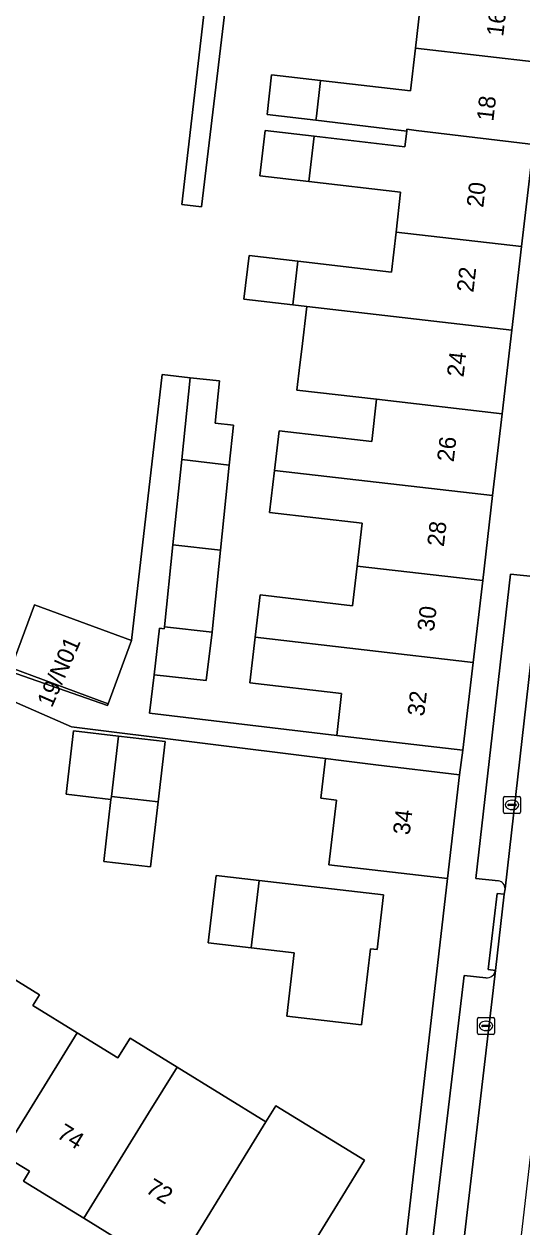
# Model space of a CAD drawing. Extents: x 161692 to 162379, y 380760 to 381678.
# Drawn here: x 161919.9 to 161949.3, y 381028.6 to 381099.9 of the extents above; entities that cross this region are included whole.
import ezdxf

# ---------------------------------------------------------------- set-up
doc = ezdxf.new("R2010")
doc.units = 0
for name, color, linetype in [('IMGEO_Erf', 7, 'Continuous'), ('IMGEO_Kolk', 7, 'Continuous'), ('IMGEO_Pand', 7, 'Continuous'), ('IMGEO_Pand_nummerreeks', 7, 'Continuous'), ('IMGEO_Parkeervlak_open', 7, 'Continuous'), ('IMGEO_Rijbaan_lokaal_open', 7, 'Continuous'), ('IMGEO_Voetpad_open', 7, 'Continuous')]:
    doc.layers.add(name, color=color, linetype=linetype)

msp = doc.modelspace()

# ---------------------------------------------------------------- linework, layer by layer
at = {"layer": 'IMGEO_Erf'}
for points in [[(161934.58, 381124.356), (161930.357, 381089.033), (161929.205, 381089.166), (161932.426, 381116.991)], [(161896.944, 381069.188), (161924.793, 381059.467), (161924.831, 381059.577), (161919.079, 381061.699), (161920.461, 381065.447), (161926.214, 381063.326), (161928.04, 381079.099), (161929.69, 381078.908), (161931.424, 381078.729), (161931.164, 381076.203), (161932.252, 381076.09), (161932.008, 381073.722), (161931.489, 381068.676), (161930.992, 381063.85), (161930.987, 381063.815), (161930.641, 381060.951), (161927.56, 381061.295), (161927.291, 381059.02), (161938.372, 381057.691), (161938.661, 381060.182), (161933.228, 381060.814), (161933.543, 381063.52), (161933.834, 381066.027), (161939.306, 381065.391), (161939.579, 381067.74), (161939.874, 381070.274), (161934.4, 381070.911), (161934.691, 381073.412), (161934.965, 381075.765), (161940.448, 381075.127), (161940.739, 381077.631), (161936.02, 381078.176), (161936.195, 381079.674), (161936.303, 381080.6), (161936.598, 381083.126), (161935.772, 381083.222), (161932.88, 381083.556), (161933.18, 381086.143), (161936.072, 381085.807), (161941.611, 381085.163), (161941.887, 381087.54), (161942.162, 381089.9), (161936.719, 381090.533), (161933.822, 381090.87), (161934.134, 381093.558), (161937.031, 381093.223), (161942.416, 381092.6), (161942.521, 381093.512), (161937.14, 381094.163), (161934.245, 381094.513), (161934.518, 381096.867), (161937.415, 381096.53), (161942.739, 381095.911), (161943.034, 381098.447), (161943.315, 381100.866)], [(161944.934, 381049.22), (161939.968, 381049.797), (161937.906, 381050.037), (161938.359, 381053.871), (161937.434, 381053.988), (161937.711, 381056.326), (161922.667, 381058.201), (161917.5, 381060.471)], [(161941.233, 381016.938), (161944.934, 381049.22)], [(161918.09, 381043.966), (161920.768, 381042.317), (161920.378, 381041.684), (161922.995, 381040.073), (161925.41, 381038.587), (161926.13, 381039.756), (161928.914, 381038.042), (161934.18, 381034.801), (161934.766, 381035.752), (161940.015, 381032.521), (161938.727, 381030.429), (161933.91, 381022.602), (161930.356, 381024.789), (161930.723, 381025.385), (161929.03, 381026.427), (161927.333, 381027.472), (161926.969, 381026.881), (161923.395, 381029.081), (161919.818, 381031.283), (161920.176, 381031.865), (161918.558, 381032.86)]]:
    msp.add_lwpolyline(points, dxfattribs=at)
for points in [[(161924.573, 381050.233), (161925, 381053.907), (161922.34, 381054.216), (161922.775, 381057.964), (161925.435, 381057.655), (161928.212, 381057.332), (161927.797, 381053.759), (161927.35, 381049.911)], [(161935.409, 381041.052), (161935.844, 381044.815), (161933.312, 381045.109), (161930.758, 381045.406), (161931.222, 381049.4), (161933.772, 381049.104), (161941.155, 381048.246), (161940.778, 381045.005), (161940.37, 381045.052), (161939.845, 381040.536)]]:
    msp.add_lwpolyline(points, close=True, dxfattribs=at)
at = {"layer": 'IMGEO_Kolk'}
for p, q in [((161948.26, 381053.155), (161948.26, 381054.007)), ((161948.335, 381054.081), (161949.187, 381054.081)), ((161948.748, 381053.861), (161948.773, 381053.861)), ((161949.261, 381054.007), (161949.261, 381053.155)), ((161949.187, 381053.081), (161948.335, 381053.081)), ((161948.519, 381053.575), (161948.519, 381053.587)), ((161948.957, 381053.538), (161948.559, 381053.538)), ((161948.562, 381053.624), (161948.96, 381053.624)), ((161948.771, 381053.301), (161948.746, 381053.301)), ((161949.003, 381053.587), (161949.003, 381053.575)), ((161946.718, 381040.056), (161946.718, 381040.908)), ((161946.793, 381040.982), (161947.645, 381040.982)), ((161947.719, 381040.908), (161947.719, 381040.056)), ((161946.977, 381040.476), (161946.977, 381040.488)), ((161947.415, 381040.439), (161947.017, 381040.439)), ((161947.02, 381040.525), (161947.418, 381040.525)), ((161947.229, 381040.202), (161947.204, 381040.202)), ((161947.206, 381040.762), (161947.231, 381040.762)), ((161947.461, 381040.488), (161947.461, 381040.476)), ((161947.645, 381039.982), (161946.793, 381039.982))]:
    msp.add_line(p, q, dxfattribs=at)
for points in [[(161948.26, 381053.155), (161948.26, 381054.007)], [(161948.335, 381054.081), (161949.187, 381054.081)], [(161949.261, 381054.007), (161949.261, 381053.155)], [(161949.187, 381053.081), (161948.335, 381053.081)], [(161946.718, 381040.056), (161946.718, 381040.908)], [(161946.793, 381040.982), (161947.645, 381040.982)], [(161947.719, 381040.908), (161947.719, 381040.056)], [(161947.645, 381039.982), (161946.793, 381039.982)]]:
    msp.add_lwpolyline(points, dxfattribs=at)
for centre, radius, start, end in [((161948.337, 381054.005), 0.0765, 91.55205, 178.44795), ((161948.337, 381054.005), 0.0765, 91.55205, 178.44795), ((161949.185, 381054.005), 0.0765, 1.55205, 88.44795), ((161949.185, 381054.005), 0.0765, 1.55205, 88.44795), ((161948.337, 381053.157), 0.0765, 181.55205, 268.44795), ((161948.337, 381053.157), 0.0765, 181.55205, 268.44795), ((161948.559, 381053.584), 0.0403, 85.87752, 175.75265), ((161948.556, 381053.574), 0.0366, 178.93798, 274.71019), ((161948.96, 381053.581), 0.043, 264.86636, 352.45326), ((161948.964, 381053.586), 0.0386, 1.73085, 96.63898), ((161949.185, 381053.157), 0.0765, 271.55205, 358.44795), ((161949.185, 381053.157), 0.0765, 271.55205, 358.44795), ((161946.795, 381040.906), 0.0765, 91.55205, 178.44795), ((161946.795, 381040.906), 0.0765, 91.55205, 178.44795), ((161947.643, 381040.906), 0.0765, 1.55205, 88.44795), ((161947.643, 381040.906), 0.0765, 1.55205, 88.44795), ((161947.017, 381040.485), 0.0403, 85.87752, 175.75265), ((161947.014, 381040.475), 0.0366, 178.93798, 274.71019), ((161947.418, 381040.482), 0.043, 264.86636, 352.45326), ((161947.422, 381040.487), 0.0386, 1.73085, 96.63898), ((161946.795, 381040.058), 0.0765, 181.55205, 268.44795), ((161946.795, 381040.058), 0.0765, 181.55205, 268.44795), ((161947.643, 381040.058), 0.0765, 271.55205, 358.44795), ((161947.643, 381040.058), 0.0765, 271.55205, 358.44795)]:
    msp.add_arc(centre, radius, start, end, dxfattribs=at)
for centre, major_axis, ratio, start_param, end_param in [((161948.747, 381053.581), (-0.387, 0.002), 0.722429, 4.712389, 7.853982), ((161948.772, 381053.581), (-0.39, 0.002), 0.717154, 1.570796, 4.712389), ((161947.205, 381040.482), (-0.387, 0.002), 0.722429, 4.712389, 7.853982), ((161947.23, 381040.482), (-0.39, 0.002), 0.717154, 1.570796, 4.712389)]:
    msp.add_ellipse(centre, major_axis=major_axis, ratio=ratio, start_param=start_param, end_param=end_param, dxfattribs=at)
at = {"layer": 'IMGEO_Pand'}
for points in [[(161951.18, 381102.61), (161938.291, 381104.099), (161937.987, 381101.486), (161943.315, 381100.866), (161943.034, 381098.447), (161950.594, 381097.573)], [(161950.594, 381097.573), (161943.034, 381098.447), (161942.739, 381095.911), (161937.415, 381096.53), (161937.169, 381094.409), (161937.154, 381094.285), (161937.14, 381094.163), (161942.521, 381093.512), (161942.535, 381093.634), (161943.075, 381093.569), (161950.03, 381092.727)], [(161937.415, 381096.53), (161934.518, 381096.867), (161934.245, 381094.513), (161937.14, 381094.163), (161937.154, 381094.285), (161937.169, 381094.409)], [(161937.031, 381093.223), (161934.134, 381093.558), (161933.822, 381090.87), (161936.719, 381090.533)], [(161950.03, 381092.727), (161943.075, 381093.569), (161942.535, 381093.634), (161942.521, 381093.512), (161942.416, 381092.6), (161937.031, 381093.223), (161936.719, 381090.533), (161942.162, 381089.9), (161941.887, 381087.54), (161949.327, 381086.68)], [(161949.327, 381086.68), (161941.887, 381087.54), (161941.611, 381085.163), (161936.072, 381085.807), (161935.772, 381083.222), (161936.598, 381083.126), (161948.751, 381081.721)], [(161936.072, 381085.807), (161933.18, 381086.143), (161932.88, 381083.556), (161935.772, 381083.222)], [(161948.751, 381081.721), (161936.598, 381083.126), (161936.303, 381080.6), (161936.195, 381079.674), (161936.02, 381078.176), (161940.739, 381077.631), (161948.175, 381076.772)], [(161929.189, 381074.048), (161932.008, 381073.722), (161932.252, 381076.09), (161931.164, 381076.203), (161931.424, 381078.729), (161929.69, 381078.908)], [(161934.691, 381073.412), (161947.611, 381071.919), (161948.175, 381076.772), (161940.739, 381077.631), (161940.448, 381075.127), (161934.965, 381075.765)], [(161931.489, 381068.676), (161932.008, 381073.722), (161929.189, 381074.048), (161928.669, 381069.002)], [(161934.691, 381073.412), (161934.4, 381070.911), (161939.874, 381070.274), (161939.579, 381067.74), (161947.025, 381066.879), (161947.611, 381071.919)], [(161928.169, 381064.141), (161930.987, 381063.815), (161930.992, 381063.85), (161931.489, 381068.676), (161928.669, 381069.002)], [(161946.46, 381062.027), (161947.025, 381066.879), (161939.579, 381067.74), (161939.306, 381065.391), (161933.834, 381066.027), (161933.543, 381063.52)], [(161924.831, 381059.577), (161926.214, 381063.326), (161920.461, 381065.447), (161919.079, 381061.699)], [(161928.169, 381064.141), (161928.157, 381064.026), (161927.869, 381064.058), (161927.56, 381061.295), (161930.641, 381060.951), (161930.987, 381063.815)], [(161933.543, 381063.52), (161933.228, 381060.814), (161938.661, 381060.182), (161938.372, 381057.691), (161940.889, 381057.398), (161945.855, 381056.821), (161946.46, 381062.027)], [(161925.435, 381057.655), (161922.775, 381057.964), (161922.34, 381054.216), (161925, 381053.907), (161925.021, 381054.086)], [(161925.435, 381057.655), (161925.021, 381054.086), (161927.797, 381053.759), (161928.212, 381057.332)], [(161945.65, 381055.374), (161940.684, 381055.951), (161938.636, 381056.209), (161937.711, 381056.326), (161937.434, 381053.988), (161938.359, 381053.871), (161937.906, 381050.037), (161939.968, 381049.797), (161944.934, 381049.22)], [(161927.797, 381053.759), (161925.021, 381054.086), (161925, 381053.907), (161924.573, 381050.233), (161927.35, 381049.911)], [(161933.312, 381045.109), (161933.772, 381049.104), (161931.222, 381049.4), (161930.758, 381045.406)], [(161941.155, 381048.246), (161933.772, 381049.104), (161933.312, 381045.109), (161935.844, 381044.815), (161935.409, 381041.052), (161939.845, 381040.536), (161940.37, 381045.052), (161940.778, 381045.005)], [(161922.995, 381040.073), (161920.378, 381041.684), (161920.768, 381042.317), (161918.09, 381043.966), (161917.703, 381043.322), (161917.552, 381043.07), (161912.981, 381035.467), (161916.572, 381033.257), (161916.94, 381033.856), (161918.558, 381032.86)], [(161918.558, 381032.86), (161920.176, 381031.865), (161919.818, 381031.283), (161923.395, 381029.081), (161927.231, 381035.309), (161928.914, 381038.042), (161926.13, 381039.756), (161925.41, 381038.587), (161922.995, 381040.073)], [(161929.03, 381026.427), (161933.478, 381033.66), (161934.18, 381034.801), (161928.914, 381038.042), (161927.231, 381035.309), (161923.395, 381029.081), (161926.969, 381026.881), (161927.333, 381027.472)], [(161929.03, 381026.427), (161930.723, 381025.385), (161930.356, 381024.789), (161933.91, 381022.602), (161938.727, 381030.429), (161940.015, 381032.521), (161934.766, 381035.752), (161934.18, 381034.801), (161933.478, 381033.66)]]:
    msp.add_lwpolyline(points, close=True, dxfattribs=at)
at = {"layer": 'IMGEO_Parkeervlak_open'}
for points in [[(161948.346, 381048.6), (161950.49, 381067.484)], [(161950.017, 381067.113), (161948.676, 381067.266), (161946.607, 381049.227), (161947.955, 381049.089)], [(161944.762, 381017.945), (161947.774, 381043.773)], [(161947.216, 381043.338), (161945.922, 381043.47), (161943.058, 381019.379)]]:
    msp.add_lwpolyline(points, dxfattribs=at)
for centre, radius, start, end in [((161947.856, 381048.609), 0.49, 358.90205, 78.38899), ((161947.274, 381043.839), 0.504, 263.35742, 352.5204)]:
    msp.add_arc(centre, radius, start, end, dxfattribs=at)
at = {"layer": 'IMGEO_Rijbaan_lokaal_open'}
msp.add_lwpolyline([(161948.215, 381018.454), (161951.537, 381047.312), (161951.635, 381048.212), (161953.839, 381067.124), (161953.854, 381067.335), (161950.519, 381067.711), (161950.49, 381067.484), (161948.346, 381048.6), (161948.302, 381048.297), (161947.774, 381043.773), (161944.762, 381017.945)], dxfattribs=at)
at = {"layer": 'IMGEO_Voetpad_open'}
for points in [[(161957.191, 381155.412), (161956.388, 381149.129), (161956.162, 381145.456), (161954.88, 381134.431), (161954.037, 381127.184), (161953.476, 381122.354), (161952.893, 381117.344), (161952.318, 381112.4), (161951.753, 381107.539), (161951.18, 381102.61), (161950.594, 381097.573), (161950.03, 381092.727), (161949.327, 381086.68), (161948.751, 381081.721), (161948.175, 381076.772), (161947.611, 381071.919), (161947.025, 381066.879), (161946.46, 381062.027), (161945.855, 381056.821), (161945.65, 381055.374), (161944.934, 381049.22), (161941.233, 381016.938)], [(161917.5, 381060.471), (161922.667, 381058.201), (161937.711, 381056.326), (161938.636, 381056.209), (161940.684, 381055.951), (161945.65, 381055.374), (161945.855, 381056.821), (161940.889, 381057.398), (161938.372, 381057.691), (161927.291, 381059.02), (161927.56, 381061.295), (161927.869, 381064.058), (161928.157, 381064.026), (161928.169, 381064.141), (161928.669, 381069.002), (161929.189, 381074.048), (161929.69, 381078.908), (161928.04, 381079.099), (161926.214, 381063.326), (161924.831, 381059.577), (161924.793, 381059.467), (161896.944, 381069.188)], [(161947.955, 381049.089), (161946.607, 381049.227), (161948.676, 381067.266), (161950.017, 381067.113)], [(161947.774, 381043.773), (161947.339, 381043.819), (161947.874, 381048.327), (161948.302, 381048.297), (161948.346, 381048.6)], [(161943.058, 381019.379), (161945.922, 381043.47), (161947.216, 381043.338)]]:
    msp.add_lwpolyline(points, dxfattribs=at)
for points in [[(161934.58, 381124.356), (161942.325, 381133.154), (161943.667, 381134.128), (161946.272, 381134.265), (161948.724, 381133.98), (161948.857, 381135.128), (161946.678, 381135.38), (161944.422, 381135.594), (161942.542, 381134.872), (161934.171, 381125.54), (161933.746, 381125.099), (161927.323, 381122.633), (161927.388, 381122.471), (161925.134, 381121.564), (161925.054, 381121.763), (161920.066, 381119.848), (161920.61, 381118.431), (161933.204, 381123.403), (161932.426, 381116.991), (161929.205, 381089.166), (161930.357, 381089.033)], [(161948.302, 381048.297), (161947.874, 381048.327), (161947.339, 381043.819), (161947.774, 381043.773)]]:
    msp.add_lwpolyline(points, close=True, dxfattribs=at)
for centre, radius, start, end in [((161947.856, 381048.609), 0.49, 358.90205, 78.38899), ((161947.274, 381043.839), 0.504, 263.35742, 352.5204)]:
    msp.add_arc(centre, radius, start, end, dxfattribs=at)

# ---------------------------------------------------------------- texts
at = {"layer": 'IMGEO_Pand_nummerreeks'}
for s, rotation, p in [('16', 83.3671, (161948.235, 381099.102)), ('18', 83.36536, (161947.651, 381094.079)), ('20', 83.36536, (161947.055, 381088.962)), ('22', 83.36536, (161946.471, 381083.931)), ('24', 83.36536, (161945.886, 381078.908)), ('26', 83.3671, (161945.302, 381073.882)), ('28', 83.3671, (161944.718, 381068.859)), ('30', 83.3671, (161944.133, 381063.833)), ('19/N01', 66.37062, (161921.496, 381059.303)), ('32', 83.3671, (161943.549, 381058.801)), ('34', 83.36536, (161942.693, 381051.767)), ('74', 328.33871, (161921.726, 381033.897)), ('72', 328.33871, (161926.992, 381030.649))]:
    msp.add_text(s, height=1, rotation=rotation, dxfattribs=at).set_placement(p)

doc.saveas('drawing.dxf')
